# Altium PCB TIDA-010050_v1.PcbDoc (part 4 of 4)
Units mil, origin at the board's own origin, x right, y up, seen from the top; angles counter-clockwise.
Board outline 2060.77 x 1300 mil, 4 copper layers (Top Layer, signal1, signal2, Bottom Layer), stack 23.6 mil thick; 58 components, 30 nets, 158 pads, 41 vias.
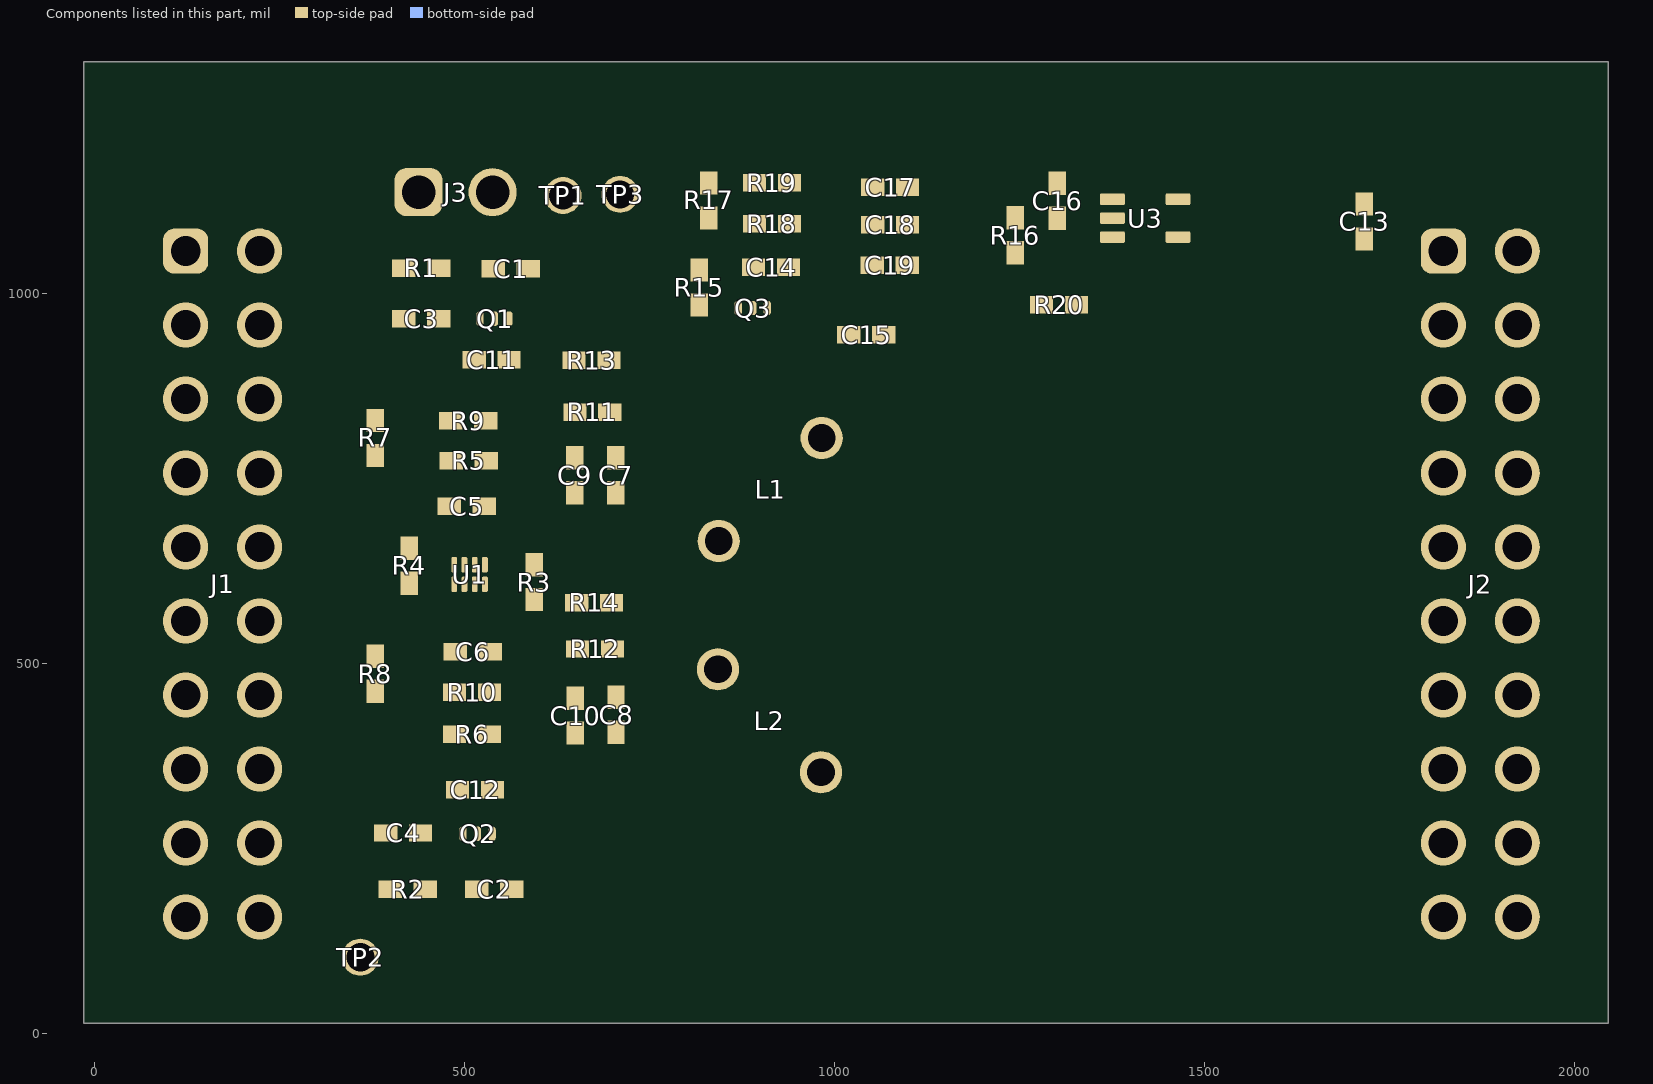
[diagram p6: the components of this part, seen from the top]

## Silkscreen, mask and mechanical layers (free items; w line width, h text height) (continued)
Drill Drawing:
  circle w10: c5313.99,3307 r9.21
  lines w10: 5304.78,3357.65 5323.2,3357.65 5313.99,3339.23 5304.78,3357.65 ; 5304.78,3380.67 5323.2,3380.67 5323.2,3399.09 5304.78,3399.09 5304.78,3380.67 ; 5304.78,3426.72 5309.38,3426.72 5313.99,3422.11 5318.59,3426.72 5323.2,3426.72 5318.59,3431.32 5323.2,3435.93 5318.59,3435.93 5313.99,3440.53 5309.38,3435.93 5304.78,3435.93 5309.38,3431.32 5304.78,3426.72 ; 5304.78,3463.55 5313.99,3468.16 5323.2,3463.55 5318.59,3472.76 5323.2,3481.97 5313.99,3477.37 5304.78,3481.97 5309.38,3472.76 5304.78,3463.55
  lines w12: 5286,3285.36 6363.16,3285.36 ; 5286,3492.56 6363.16,3492.56 ; 5398.62,3243.92 5398.62,3534 ; 5509.29,3243.92 5509.29,3534 ; 5721.48,3243.92 5721.48,3534 ; 5807.86,3243.92 5807.86,3534 ; 5932.91,3243.92 5932.91,3534 ; 6174.35,3243.92 6174.35,3534 ; 5286,3243.92 6363.16,3243.92 6363.16,3534 5286,3534 5286,3243.92
  text "Symbol" at 5310.86,3504.99 h24
  text "Quantity" at 5411.05,3504.99 h24
  text "Finished Hole Size" at 5521.72,3504.99 h24
  text "Plated" at 5733.91,3504.99 h24
  text "Hole Type" at 5820.29,3504.99 h24
  text "Drill Layer Pair" at 5945.34,3504.99 h24
  text "Hole Tolerance" at 6186.78,3504.99 h24
  text "41" at 5411.05,3463.55 h20
  text "8.00mil (0.203mm)" at 5521.72,3463.55 h20
  text "PTH" at 5733.91,3463.55 h20
  text "Round" at 5820.29,3463.55 h20
  text "Top Layer - Bottom Layer" at 5945.34,3463.55 h20
  text "5" at 5411.05,3422.11 h20
  text "37.40mil (0.950mm)" at 5521.72,3422.11 h20
  text "PTH" at 5733.91,3422.11 h20
  text "Round" at 5820.29,3422.11 h20
  text "Top Layer - Bottom Layer" at 5945.34,3422.11 h20
  text "2" at 5411.05,3380.67 h20
  text "37.99mil (0.965mm)" at 5521.72,3380.67 h20
  text "PTH" at 5733.91,3380.67 h20
  text "Round" at 5820.29,3380.67 h20
  text "Top Layer - Bottom Layer" at 5945.34,3380.67 h20
  text "40" at 5411.05,3339.23 h20
  text "40.16mil (1.020mm)" at 5521.72,3339.23 h20
  text "PTH" at 5733.91,3339.23 h20
  text "Round" at 5820.29,3339.23 h20
  text "Top Layer - Bottom Layer" at 5945.34,3339.23 h20
  text "2" at 5411.05,3297.79 h20
  text "45.28mil (1.150mm)" at 5521.72,3297.79 h20
  text "PTH" at 5733.91,3297.79 h20
  text "Round" at 5820.29,3297.79 h20
  text "Top Layer - Bottom Layer" at 5945.34,3297.79 h20
  text "90 Total" at 5411.05,3256.35 h20
  text ".Layer_Name" at 449,-564.49 h20
Mechanical 17:
  text ".Layer_Name" at 577,-858.49 h20
Mechanical 18:
  text ".Layer_Name" at 577,-858.49 h20
Mechanical 19:
  text ".Layer_Name" at 577,-858.49 h20

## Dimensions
-14.23,11.77 to 2045.77,13 on M2 Board Dimensions
-23,11.96 to -23,1311.96 on M2 Board Dimensions
0,-400 to 1000,-400 on M2 Board Dimensions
